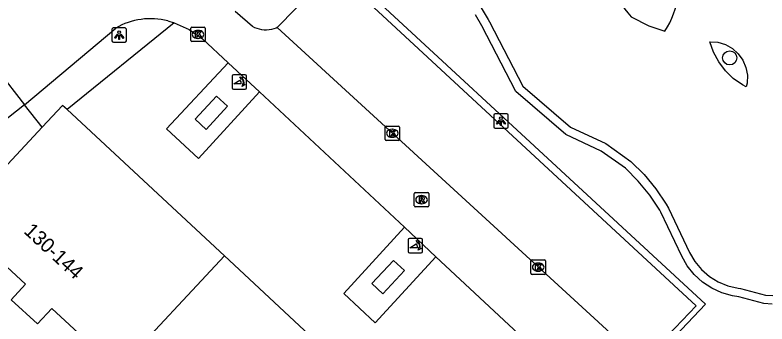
# Model space of a CAD drawing. Extents: x 159222 to 160346, y 381249 to 382166.
# Drawn here: x 159841.6 to 159893.6, y 381788.8 to 381810.2 of the extents above; entities that cross this region are included whole.
import ezdxf

# ---------------------------------------------------------------- set-up
doc = ezdxf.new("R2010")
doc.units = 0
for name, color, linetype in [('IMGEO_Boom', 7, 'Continuous'), ('IMGEO_Groenvoorziening', 7, 'Continuous'), ('IMGEO_Haag', 7, 'Continuous'), ('IMGEO_Kolk', 7, 'Continuous'), ('IMGEO_Lichtpunt', 7, 'Continuous'), ('IMGEO_Pand', 7, 'Continuous'), ('IMGEO_Pand_nummerreeks', 7, 'Continuous'), ('IMGEO_Poller', 7, 'Continuous'), ('IMGEO_Rijbaan_lokaal_open', 7, 'Continuous'), ('IMGEO_Rioolput', 7, 'Continuous'), ('IMGEO_Voetpad_halfverhard', 7, 'Continuous'), ('IMGEO_Voetpad_open', 7, 'Continuous')]:
    doc.layers.add(name, color=color, linetype=linetype)

msp = doc.modelspace()

# ---------------------------------------------------------------- linework, layer by layer
at = {"layer": 'IMGEO_Boom'}
msp.add_circle((159891.001, 381807.191), 0.489, dxfattribs=at)
at = {"layer": 'IMGEO_Groenvoorziening'}
msp.add_lwpolyline([(159890.186, 381808.271), (159890.71, 381808.111), (159891.187, 381807.842), (159891.595, 381807.475), (159891.913, 381807.029), (159892.126, 381806.524), (159892.225, 381805.985), (159892.205, 381805.437), (159892.153, 381805.178), (159891.877, 381805.33), (159891.252, 381805.77), (159890.703, 381806.302), (159890.244, 381806.914), (159889.887, 381807.59), (159889.639, 381808.313), (159890.186, 381808.271)], dxfattribs=at)
at = {"layer": 'IMGEO_Haag'}
for points in [[(159873.805, 381810.661), (159874.301, 381809.851), (159874.384, 381809.69), (159876.686, 381805.236), (159879.987, 381802.396), (159882.421, 381801.257), (159884.168, 381800.02), (159885.075, 381799.112), (159885.893, 381798.124), (159886.615, 381797.064), (159886.775, 381796.796), (159888.225, 381793.724), (159888.588, 381793.097), (159889.049, 381792.539), (159889.596, 381792.065), (159890.214, 381791.687), (159890.885, 381791.416), (159891.592, 381791.26), (159891.752, 381791.241), (159893.482, 381790.771), (159893.994, 381790.754)], [(159893.934, 381790.149), (159893.356, 381790.183), (159891.641, 381790.65), (159891.206, 381790.717), (159890.463, 381790.926), (159889.761, 381791.247), (159889.117, 381791.674), (159888.548, 381792.194), (159888.065, 381792.797), (159887.682, 381793.467), (159886.244, 381796.515), (159886.167, 381796.645), (159885.469, 381797.688), (159884.675, 381798.66), (159883.791, 381799.552), (159882.118, 381800.736), (159879.658, 381801.887), (159876.207, 381804.857), (159873.849, 381809.419), (159873.416, 381810.166)]]:
    msp.add_lwpolyline(points, dxfattribs=at)
at = {"layer": 'IMGEO_Kolk'}
for p, q in [((159853.712, 381808.389), (159853.712, 381809.241)), ((159853.787, 381809.315), (159854.639, 381809.315)), ((159854.2, 381809.095), (159854.225, 381809.095)), ((159854.713, 381809.241), (159854.713, 381808.389)), ((159854.639, 381808.315), (159853.787, 381808.315)), ((159854.223, 381808.535), (159854.198, 381808.535)), ((159867.156, 381801.547), (159867.156, 381802.399)), ((159867.231, 381802.473), (159868.083, 381802.473)), ((159868.157, 381802.399), (159868.157, 381801.547)), ((159867.644, 381802.253), (159867.669, 381802.253)), ((159868.083, 381801.473), (159867.231, 381801.473)), ((159867.667, 381801.693), (159867.642, 381801.693)), ((159877.253, 381792.284), (159877.253, 381793.136)), ((159877.328, 381793.21), (159878.18, 381793.21)), ((159877.741, 381792.99), (159877.766, 381792.99)), ((159878.254, 381793.136), (159878.254, 381792.284)), ((159878.18, 381792.21), (159877.328, 381792.21)), ((159877.764, 381792.43), (159877.739, 381792.43))]:
    msp.add_line(p, q, dxfattribs=at)
for points in [[(159853.712, 381808.389), (159853.712, 381809.241)], [(159853.787, 381809.315), (159854.639, 381809.315)], [(159854.713, 381809.241), (159854.713, 381808.389)], [(159854.033, 381809.015), (159854.156, 381809.015), (159854.156, 381808.864), (159854.286, 381809.015), (159854.45, 381809.015), (159854.304, 381808.864), (159854.457, 381808.615), (159854.305, 381808.615), (159854.22, 381808.779), (159854.156, 381808.712), (159854.156, 381808.615), (159854.033, 381808.615), (159854.033, 381809.015)], [(159854.639, 381808.315), (159853.787, 381808.315)], [(159867.156, 381801.547), (159867.156, 381802.399)], [(159867.231, 381802.473), (159868.083, 381802.473)], [(159868.157, 381802.399), (159868.157, 381801.547)], [(159867.477, 381802.173), (159867.6, 381802.173), (159867.6, 381802.022), (159867.73, 381802.173), (159867.894, 381802.173), (159867.748, 381802.022), (159867.901, 381801.773), (159867.749, 381801.773), (159867.664, 381801.937), (159867.6, 381801.87), (159867.6, 381801.773), (159867.477, 381801.773), (159867.477, 381802.173)], [(159868.083, 381801.473), (159867.231, 381801.473)], [(159877.253, 381792.284), (159877.253, 381793.136)], [(159877.328, 381793.21), (159878.18, 381793.21)], [(159878.254, 381793.136), (159878.254, 381792.284)], [(159877.574, 381792.91), (159877.697, 381792.91), (159877.697, 381792.759), (159877.827, 381792.91), (159877.991, 381792.91), (159877.845, 381792.759), (159877.998, 381792.51), (159877.846, 381792.51), (159877.761, 381792.674), (159877.697, 381792.607), (159877.697, 381792.51), (159877.574, 381792.51), (159877.574, 381792.91)], [(159878.18, 381792.21), (159877.328, 381792.21)]]:
    msp.add_lwpolyline(points, dxfattribs=at)
for centre, start, end in [((159853.789, 381809.239), 91.552, 178.448), ((159853.789, 381809.239), 91.552, 178.448), ((159854.637, 381809.239), 1.552, 88.448), ((159854.637, 381809.239), 1.552, 88.448), ((159853.789, 381808.391), 181.552, 268.448), ((159853.789, 381808.391), 181.552, 268.448), ((159854.637, 381808.391), 271.552, 358.448), ((159854.637, 381808.391), 271.552, 358.448), ((159867.233, 381802.397), 91.552, 178.448), ((159867.233, 381802.397), 91.552, 178.448), ((159868.081, 381802.397), 1.552, 88.448), ((159868.081, 381802.397), 1.552, 88.448), ((159867.233, 381801.549), 181.552, 268.448), ((159867.233, 381801.549), 181.552, 268.448), ((159868.081, 381801.549), 271.552, 358.448), ((159868.081, 381801.549), 271.552, 358.448), ((159877.33, 381793.134), 91.552, 178.448), ((159877.33, 381793.134), 91.552, 178.448), ((159878.178, 381793.134), 1.552, 88.448), ((159878.178, 381793.134), 1.552, 88.448), ((159877.33, 381792.286), 181.552, 268.448), ((159877.33, 381792.286), 181.552, 268.448), ((159878.178, 381792.286), 271.552, 358.448), ((159878.178, 381792.286), 271.552, 358.448)]:
    msp.add_arc(centre, 0.0765, start, end, dxfattribs=at)
for centre, major_axis, ratio, start_param, end_param in [((159854.199, 381808.815), (-0.387, 0.002), 0.722429, 4.712389, 7.853982), ((159854.224, 381808.815), (-0.39, 0.002), 0.717154, 1.570796, 4.712389), ((159867.643, 381801.973), (-0.387, 0.002), 0.722429, 4.712389, 7.853982), ((159867.668, 381801.973), (-0.39, 0.002), 0.717154, 1.570796, 4.712389), ((159877.74, 381792.71), (-0.387, 0.002), 0.722429, 4.712389, 7.853982), ((159877.765, 381792.71), (-0.39, 0.002), 0.717154, 1.570796, 4.712389)]:
    msp.add_ellipse(centre, major_axis=major_axis, ratio=ratio, start_param=start_param, end_param=end_param, dxfattribs=at)
at = {"layer": 'IMGEO_Lichtpunt'}
for p, q in [((159848.26, 381809.169), (159848.26, 381808.362)), ((159848.26, 381809.169), (159848.26, 381808.362)), ((159849.162, 381809.264), (159848.354, 381809.264)), ((159849.162, 381809.264), (159848.354, 381809.264)), ((159849.256, 381808.362), (159849.256, 381809.169)), ((159849.256, 381808.362), (159849.256, 381809.169)), ((159848.354, 381808.268), (159849.162, 381808.268)), ((159848.354, 381808.268), (159849.162, 381808.268)), ((159874.676, 381803.224), (159874.676, 381802.417)), ((159874.676, 381803.224), (159874.676, 381802.417)), ((159875.578, 381803.319), (159874.77, 381803.319)), ((159875.578, 381803.319), (159874.77, 381803.319)), ((159875.672, 381802.417), (159875.672, 381803.224)), ((159875.672, 381802.417), (159875.672, 381803.224)), ((159874.77, 381802.323), (159875.578, 381802.323)), ((159874.77, 381802.323), (159875.578, 381802.323))]:
    msp.add_line(p, q, dxfattribs=at)
for points in [[(159848.634, 381808.833), (159848.673, 381808.805), (159848.485, 381808.543), (159848.447, 381808.57), (159848.634, 381808.833)], [(159848.736, 381808.785), (159848.783, 381808.785), (159848.783, 381808.463), (159848.736, 381808.463), (159848.736, 381808.785)], [(159848.846, 381808.805), (159848.884, 381808.832), (159849.071, 381808.57), (159849.032, 381808.542), (159848.846, 381808.805)], [(159875.05, 381802.888), (159875.089, 381802.86), (159874.901, 381802.598), (159874.863, 381802.625), (159875.05, 381802.888)], [(159875.262, 381802.86), (159875.3, 381802.887), (159875.487, 381802.625), (159875.448, 381802.597), (159875.262, 381802.86)], [(159875.152, 381802.84), (159875.199, 381802.84), (159875.199, 381802.518), (159875.152, 381802.518), (159875.152, 381802.84)]]:
    msp.add_lwpolyline(points, dxfattribs=at)
for centre in [(159848.759, 381808.967), (159875.175, 381803.022)]:
    msp.add_circle(centre, 0.0994, dxfattribs=at)
for centre, start, end in [((159848.354, 381809.169), 90, 180), ((159848.354, 381809.169), 90, 180), ((159849.162, 381809.169), 0, 90), ((159849.162, 381809.169), 0, 90), ((159848.354, 381808.362), 180, 270), ((159848.354, 381808.362), 180, 270), ((159849.162, 381808.362), 270, 0), ((159849.162, 381808.362), 270, 360), ((159874.77, 381803.224), 90, 180), ((159874.77, 381803.224), 90, 180), ((159875.578, 381803.224), 0, 90), ((159875.578, 381803.224), 0, 90), ((159874.77, 381802.417), 180, 270), ((159874.77, 381802.417), 180, 270), ((159875.578, 381802.417), 270, 0), ((159875.578, 381802.417), 270, 360)]:
    msp.add_arc(centre, 0.0946, start, end, dxfattribs=at)
at = {"layer": 'IMGEO_Pand'}
for points in [[(159840.364, 381806.301), (159842.218, 381803.935)], [(159842.218, 381803.935), (159837.309, 381800.087), (159835.454, 381802.453)], [(159845.153, 381803.609), (159844.839, 381803.901), (159843.436, 381802.394)], [(159845.153, 381803.609), (159856.038, 381793.481)], [(159848.695, 381785.59), (159844.089, 381789.85), (159843.097, 381788.778), (159841.291, 381790.448), (159842.281, 381791.521), (159837.463, 381795.978), (159843.436, 381802.394)], [(159856.038, 381793.481), (159848.695, 381785.59)], [(159856.038, 381793.481), (159867.103, 381783.184)]]:
    msp.add_lwpolyline(points, dxfattribs=at)
at = {"layer": 'IMGEO_Poller'}
for p, q in [((159857.468, 381806.029), (159856.66, 381806.029)), ((159857.468, 381806.029), (159856.66, 381806.029)), ((159856.566, 381805.934), (159856.566, 381805.127)), ((159856.566, 381805.934), (159856.566, 381805.127)), ((159857.562, 381805.127), (159857.562, 381805.934)), ((159857.562, 381805.127), (159857.562, 381805.934)), ((159856.66, 381805.032), (159857.468, 381805.032)), ((159856.66, 381805.032), (159857.468, 381805.032)), ((159868.755, 381794.605), (159868.755, 381793.798)), ((159868.755, 381794.605), (159868.755, 381793.798)), ((159869.657, 381794.7), (159868.849, 381794.7)), ((159869.657, 381794.7), (159868.849, 381794.7)), ((159869.751, 381793.798), (159869.751, 381794.605)), ((159869.751, 381793.798), (159869.751, 381794.605)), ((159868.849, 381793.703), (159869.657, 381793.703)), ((159868.849, 381793.703), (159869.657, 381793.703))]:
    msp.add_line(p, q, dxfattribs=at)
for points in [[(159857.201, 381805.385), (159856.688, 381805.385), (159857.118, 381805.66)], [(159857.245, 381805.758), (159857.233, 381805.685), (159857.108, 381805.89)], [(159857.108, 381805.89), (159857.339, 381805.824), (159857.268, 381805.792)], [(159857.261, 381805.213), (159857.327, 381805.444), (159857.357, 381805.376)], [(159857.393, 381805.349), (159857.465, 381805.338), (159857.261, 381805.213)], [(159869.434, 381794.429), (159869.422, 381794.356), (159869.297, 381794.561)], [(159869.297, 381794.561), (159869.528, 381794.495), (159869.457, 381794.463)], [(159869.39, 381794.056), (159868.877, 381794.056), (159869.307, 381794.331)], [(159869.45, 381793.884), (159869.516, 381794.115), (159869.546, 381794.047)], [(159869.582, 381794.02), (159869.654, 381794.009), (159869.45, 381793.884)]]:
    msp.add_lwpolyline(points, dxfattribs=at)
for centre, radius, start, end in [((159856.66, 381805.934), 0.0946, 90, 180), ((159856.66, 381805.934), 0.0946, 90, 180), ((159857.468, 381805.934), 0.0946, 0, 90), ((159857.468, 381805.934), 0.0946, 0, 90), ((159856.873, 381805.435), 0.332, 351.3247, 42.4854), ((159856.887, 381805.445), 0.476, 351.7527, 41.1691), ((159856.887, 381805.445), 0.516, 349.3569, 42.2912), ((159856.66, 381805.127), 0.0946, 180, 270), ((159856.66, 381805.127), 0.0946, 180, 270), ((159857.468, 381805.127), 0.0946, 270, 0), ((159857.468, 381805.127), 0.0946, 270, 0), ((159868.849, 381794.605), 0.0946, 90, 180), ((159868.849, 381794.605), 0.0946, 90, 180), ((159869.657, 381794.605), 0.0946, 0, 90), ((159869.657, 381794.605), 0.0946, 0, 90), ((159869.062, 381794.106), 0.332, 351.3247, 42.4854), ((159869.076, 381794.116), 0.476, 351.7527, 41.1691), ((159869.076, 381794.116), 0.516, 349.3569, 42.2912), ((159868.849, 381793.798), 0.0946, 180, 270), ((159868.849, 381793.798), 0.0946, 180, 270), ((159869.657, 381793.798), 0.0946, 270, 0), ((159869.657, 381793.798), 0.0946, 270, 0)]:
    msp.add_arc(centre, radius, start, end, dxfattribs=at)
at = {"layer": 'IMGEO_Rijbaan_lokaal_open'}
for points in [[(159859.685, 381809.285), (159859.613, 381809.254), (159859.455, 381809.198), (159859.292, 381809.156), (159859.126, 381809.129), (159858.959, 381809.116), (159858.79, 381809.119), (159858.623, 381809.137), (159858.458, 381809.169), (159858.297, 381809.216), (159858.14, 381809.278), (159857.99, 381809.353), (159856.777, 381810.409)], [(159852.118, 381809.746), (159852.558, 381809.614)], [(159852.558, 381809.614), (159853.599, 381809.162), (159854.533, 381808.516), (159856.308, 381806.857)], [(159842.218, 381803.935), (159848.527, 381809.25)], [(159884.961, 381786.098), (159859.685, 381809.285)], [(159856.308, 381806.857), (159858.477, 381804.83)], [(159858.477, 381804.83), (159868.497, 381795.466)], [(159868.497, 381795.466), (159870.673, 381793.433)], [(159870.673, 381793.433), (159878.074, 381786.517)]]:
    msp.add_lwpolyline(points, dxfattribs=at)
msp.add_arc((159850.92, 381805.175), 4.726, 75.3113, 120.4169, dxfattribs=at)
at = {"layer": 'IMGEO_Rioolput'}
for p, q in [((159869.181, 381796.95), (159869.181, 381797.802)), ((159869.256, 381797.876), (159870.108, 381797.876)), ((159869.669, 381797.656), (159869.694, 381797.656)), ((159870.182, 381797.802), (159870.182, 381796.95)), ((159870.108, 381796.876), (159869.256, 381796.876)), ((159869.692, 381797.096), (159869.667, 381797.096))]:
    msp.add_line(p, q, dxfattribs=at)
for points in [[(159869.181, 381796.95), (159869.181, 381797.802)], [(159869.256, 381797.876), (159870.108, 381797.876)], [(159870.182, 381797.802), (159870.182, 381796.95)], [(159869.77, 381797.574), (159869.518, 381797.576), (159869.518, 381797.176)], [(159869.518, 381797.176), (159869.642, 381797.176), (159869.642, 381797.338), (159869.653, 381797.338)], [(159869.696, 381797.495), (159869.642, 381797.495), (159869.642, 381797.414)], [(159869.642, 381797.414), (159869.694, 381797.414)], [(159869.7, 381797.309), (159869.771, 381797.176), (159869.911, 381797.176), (159869.846, 381797.302)], [(159870.108, 381796.876), (159869.256, 381796.876)]]:
    msp.add_lwpolyline(points, dxfattribs=at)
for centre, radius, start, end in [((159869.258, 381797.8), 0.0765, 91.552, 178.448), ((159869.258, 381797.8), 0.0765, 91.552, 178.448), ((159870.106, 381797.8), 0.0765, 1.552, 88.448), ((159870.106, 381797.8), 0.0765, 1.552, 88.448), ((159869.652, 381797.285), 0.0533, 26.0293, 88.6989), ((159869.678, 381797.603), 0.19, 274.7715, 282.9687), ((159869.702, 381797.399), 0.0964, 77.0061, 93.1865), ((159869.716, 381797.456), 0.0378, 276.6634, 79.6772), ((159869.769, 381797.464), 0.109, 350.3612, 89.416), ((159869.767, 381797.464), 0.112, 277.5842, 350.9817), ((159869.751, 381797.249), 0.108, 29.5134, 73.7905), ((159869.258, 381796.952), 0.0765, 181.552, 268.448), ((159869.258, 381796.952), 0.0765, 181.552, 268.448), ((159870.106, 381796.952), 0.0765, 271.552, 358.448), ((159870.106, 381796.952), 0.0765, 271.552, 358.448)]:
    msp.add_arc(centre, radius, start, end, dxfattribs=at)
for centre, major_axis, ratio, start_param, end_param in [((159869.668, 381797.376), (-0.387, 0.002), 0.722429, 4.712389, 7.853982), ((159869.693, 381797.376), (-0.39, 0.002), 0.717154, 1.570796, 4.712389)]:
    msp.add_ellipse(centre, major_axis=major_axis, ratio=ratio, start_param=start_param, end_param=end_param, dxfattribs=at)
at = {"layer": 'IMGEO_Voetpad_halfverhard'}
msp.add_lwpolyline([(159884.179, 381810.043), (159885.405, 381809.408), (159886.516, 381809.038)], dxfattribs=at)
for centre, radius, start, end in [((159889.818, 381815.095), 7.571, 181.0395, 221.8582), ((159881.226, 381812.428), 6.283, 327.3421, 16.3883)]:
    msp.add_arc(centre, radius, start, end, dxfattribs=at)
at = {"layer": 'IMGEO_Voetpad_open'}
for points in [[(159857.487, 381819.613), (159889.337, 381790.147), (159885.563, 381786.183), (159885.473, 381786.053), (159885.395, 381785.916), (159885.33, 381785.772), (159885.278, 381785.623), (159885.239, 381785.47), (159885.214, 381785.314), (159885.203, 381785.157), (159885.207, 381784.999), (159885.224, 381784.842), (159885.255, 381784.687), (159885.3, 381784.536), (159885.359, 381784.389), (159885.416, 381784.273), (159888.474, 381781.541)], [(159859.685, 381809.285), (159863.597, 381813.276), (159888.672, 381790.031), (159885.291, 381786.48), (159884.961, 381786.098)], [(159852.558, 381809.614), (159845.153, 381803.609)], [(159858.477, 381804.83), (159854.243, 381800.238), (159852.037, 381802.271), (159856.308, 381806.857)], [(159854.779, 381802.235), (159854.007, 381802.947), (159855.485, 381804.55), (159856.257, 381803.838), (159854.779, 381802.235)], [(159843.436, 381802.394), (159842.218, 381803.935)], [(159870.673, 381793.433), (159866.474, 381788.854), (159864.295, 381790.881), (159868.497, 381795.466)], [(159867.011, 381790.869), (159866.24, 381791.565), (159867.729, 381793.176), (159868.5, 381792.48), (159867.011, 381790.869)]]:
    msp.add_lwpolyline(points, dxfattribs=at)

# ---------------------------------------------------------------- texts
at = {"layer": 'IMGEO_Pand_nummerreeks'}
msp.add_text('130-144', height=1, rotation=317.2368, dxfattribs=at).set_placement((159842.098, 381795.124))

doc.saveas('drawing.dxf')
